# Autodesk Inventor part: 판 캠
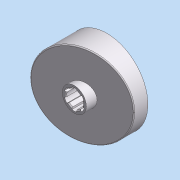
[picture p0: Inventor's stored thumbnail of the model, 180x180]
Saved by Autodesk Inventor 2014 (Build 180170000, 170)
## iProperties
Created: 2012-05
Part Number: 판 캠
Document SubType Name: 모델링
Designer: SeoGD™
Material: 강철
Mass: 86.8264 g
Surface Area: 331.303 cm^2
Volume: 86.8264 cm^3
Density: 1 g/cm^3
Appearance: 알루미늄 - 평지
변환 표준: STEP AP214IS
파일 이름: C:\Users\SeoGD\Desktop\?쒗뿕\??stp
전처리기: Build: 253, Release: 2010 SP1 - Date: Wed 07/29/2009
전송 단위: 밀리미터
불확실성: 0.01
Author: SeoGD™
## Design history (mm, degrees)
node "작업 평면4"
sketch "스케치1"
  geometry: C1 r 44.5 at (0, 0); 1 further point
  constraints: 1 centre point, 1 coincident
  dimensions: "d25" = 89 diameter of C1
extrude "돌출1" new body sketch "스케치1" distance "d1" = 40; taper "d2" = 0 deg
sketch "스케치2"
  geometry: L1 (-44.5, 15)-(44.5, 38.847); L2 (-44.5, 0)-(-44.5, 40) reference; L3 (-44.5, 40)-(44.5, 40) reference; L4 (44.5, 0)-(44.5, 40) reference; 1 further point
  constraints: 2 end point, 2 point on line
  dimensions: "d26" = 15 distance of L2.start L1.start; "d27" = 75 deg angle of L1 L2
extrude "돌출2" cut sketch "스케치2" stored distance "d5" = 40; taper "d6" = 0 deg
node "작업 평면1"
sketch "스케치3"
  geometry: C1 r 13 at (0, 0); 1 further point
  constraints: 1 centre point, 1 coincident
  dimensions: "d9" = 26 diameter of C1
extrude "돌출3" join sketch "스케치3" distance "d10" = 38; taper "d11" = 0 deg
hole "구멍1" diameter "d14" = 18; stored, may be unused: countersink angle "d18" = 90 deg, drill point angle "d20" = 118 deg; dims "d12" = 10, "d13" = 10, "d15" = 6, "d16" = 4, "d17" = 2, "d19" = 8
feature "쉘2" dims "d29" = 5
sketch "스케치6"
  geometry: C1 r 17.5 at (0, 0); C2 r 14 at (0, 0) reference; 1 further point
  constraints: 1 centre point, 1 coincident
  dimensions: "d28" = 35 diameter of C1
extrude "돌출4" join sketch "스케치6" stored distance "d30" = 38; taper "d31" = 0 deg
fillet "모깎기1" dims "d32" = 3
chamfer "모따기1" distance "d21" = 1; stored, may be unused: second distance "d22" = 2, angle "d23" = 45 deg
sketch "스케치7"
  geometry: L1 (-12.374, 12.374)-(-27.931, 27.931); A1 r 39.5 centre (0, 0) between (-27.931, 27.931) and (0, 39.5) reference; 2 further points
  constraints: 2 end point, 2 point on circle, 1 point on line, 1 vertical alignment, 2 other
  dimensions: "d33" = 45 deg dimension on point (0, 0) L1.start A1.end
feature "리브1" sketch "스케치7" dims "d34" = 5, "d35" = 1, "d36" = 0
fillet "모깎기2" dims "d37" = 3
sketch "스케치8"
  geometry: L1 (2.5, 10.712)-(2.5, 8.646); L2 (-2.5, 10.712)-(-2.5, 8.646); A1 r 11 centre (0, 0) between (2.5, 10.712) and (-2.5, 10.712); A2 r 9 centre (0, 0) between (2.5, 8.646) and (-2.5, 8.646) reference; 1 further point
  constraints: 4 end point, 4 point on circle, 2 parallel, 1 centre point, 1 coincident, 1 vertical
  dimensions: "d41" = 22 diameter of A1; "d42" = 5 distance between parallel lines of L1 L2
extrude "돌출5" cut sketch "스케치8" stored distance "d43" = 38; taper "d44" = 0 deg
fillet "모깎기3" dims "d48" = 1
node "솔리드1"
node "솔리드 본체"
node "곡면 본체"
pattern_circular "원형 패턴1" dims angle "d39" = 360 deg
pattern_circular "원형 패턴2" dims angle "d46" = 360 deg
node "솔리드2"
